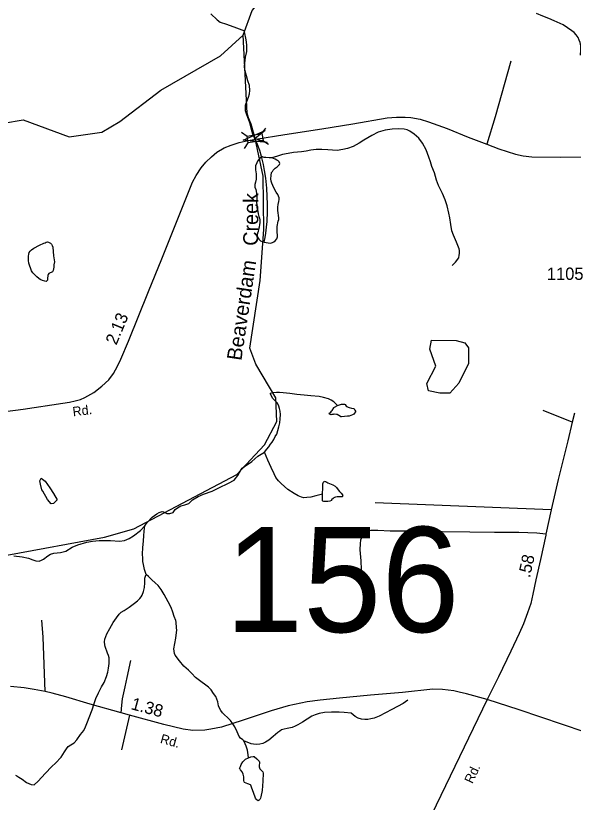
# Model space of a CAD drawing. Extents: x 2206922 to 2357709, y 510027 to 673830.
# Drawn here: x 2224516 to 2230172, y 549625 to 557602 of the extents above; entities that cross this region are included whole.
import ezdxf

# ---------------------------------------------------------------- set-up
doc = ezdxf.new("R2010")
doc.units = 0
for name, color, linetype in [('Exist Hydrographic Creek Single Shore', 7, 'Continuous'), ('Exist Hydrographic Creek Single Shore Label', 7, 'Continuous'), ('Exist Hydrographic Misc Water Feature', 7, 'Continuous'), ('Exist Hydrographic Pond Under 1500 Sq Ft', 7, 'Continuous'), ('Exist Road Non-System Type 51', 7, 'Continuous'), ('Exist Road Secondary Mileage Hundredths English Label', 7, 'Continuous'), ('Exist Road Secondary Structure Standard Bridge Attributed CELL', 7, 'Continuous'), ('Exist Road Secondary Structure Standard Bridge CELL', 7, 'Continuous'), ('Exist Road Secondary Structure Standard Bridge Number Label', 7, 'Continuous'), ('Exist Road Secondary Type 51 Attributed', 7, 'Continuous'), ('Exist Road Secondary Type 51 Label', 7, 'Continuous'), ('Exist Road Secondary Type 51 Number Label', 7, 'Continuous')]:
    doc.layers.add(name, color=color, linetype=linetype)

msp = doc.modelspace()

# ---------------------------------------------------------------- linework, layer by layer
at = {"layer": 'Exist Hydrographic Creek Single Shore'}
for points in [[(2226824.2, 557404.7), (2226914.2, 557655.5), (2227368.2, 558177.7), (2227799.2, 558372.3)], [(2223926.2, 556098.8), (2224069.1, 556168.1), (2224391.1, 556512.5), (2224590.2, 556544.6), (2225058.1, 556374.4), (2225391.1, 556420.2), (2225573.2, 556528), (2225987.2, 556847.6), (2226593.1, 557196.2), (2226824.2, 557404.7)], [(2223955.1, 551959), (2224427.1, 552129.9), (2225416.1, 552313.3), (2225715.1, 552399), (2226760.2, 552948.7), (2227041.1, 553251.3), (2227164.2, 553485), (2227154.1, 553727.9), (2226951.1, 554066.6), (2226892.1, 554231.7), (2226994.2, 554915.1), (2227032.1, 555432.6), (2227027.2, 555973.9), (2226945, 556358.4), (2226903.2, 556503.4), (2226877.1, 556567.2), (2226864.2, 556613.5), (2226824.2, 557404.7)]]:
    msp.add_lwpolyline(points, dxfattribs=at)
at = {"layer": 'Exist Hydrographic Misc Water Feature'}
for points in [[(2226494.9, 557620.4), (2226561.1, 557560.9), (2226589, 557535.2), (2226655.7, 557515.8), (2226755.5, 557478.4), (2226835.7, 557449.3)], [(2230244.3, 557201.1), (2230248.2, 557253.2), (2230247.3, 557297.1), (2230241.2, 557328.9), (2230232.8, 557354.9), (2230220.5, 557380.7), (2230200.6, 557408.8), (2230180.7, 557432.5), (2230158.1, 557450.1), (2230067.7, 557509.5), (2229977.7, 557550.7), (2229923.4, 557572.3), (2229863.1, 557597.6), (2229798.7, 557625.1)], [(2227010.4, 556175.2), (2226991.7, 556234.7), (2226969, 556296.6), (2226922.4, 556400.1), (2226907.9, 556448.1), (2226889.6, 556514.2), (2226860.7, 556596), (2226848.4, 556637.6), (2226845.9, 556673.6), (2226848, 556695.6), (2226859.5, 556731.6), (2226877.5, 556775.9), (2226887, 556809.8), (2226890.4, 556843.7), (2226886.3, 556895.8), (2226872, 556941.8), (2226857.6, 556993.4), (2226841.2, 557053.5), (2226836.7, 557085.4), (2226840.2, 557121.4), (2226845.9, 557181.4), (2226859.7, 557237.7), (2226858.9, 557307.5), (2226854.3, 557357.2), (2226837.9, 557439.3), (2226835.7, 557449.3)], [(2228944.4, 555067.5), (2228978.1, 555103.8), (2229009.6, 555146.1), (2229015.4, 555172), (2229019.1, 555192.1), (2229017, 555220), (2229015, 555236.1), (2228986.3, 555303.7), (2228955.7, 555377.7), (2228939.5, 555421.5), (2228930.7, 555483.2), (2228920.5, 555551.2), (2228910, 555599), (2228893.4, 555674.9), (2228872.7, 555734.5), (2228846.2, 555800.5), (2228805.6, 555880), (2228785.1, 555933.8), (2228763, 556009.7), (2228736.1, 556073.4), (2228724.2, 556119), (2228707.4, 556169), (2228681, 556242.7), (2228642.2, 556310.6), (2228605.9, 556360.3), (2228557.5, 556399.6), (2228515.3, 556429.5), (2228485.1, 556445), (2228455, 556452.8), (2228397, 556454.2), (2228335.4, 556451.7), (2228263.5, 556441.1), (2228193.7, 556420.8), (2228128.1, 556386.1), (2228046.3, 556339.6), (2227998.7, 556309.1), (2227938.7, 556274.8), (2227883.1, 556254.4), (2227834.9, 556243.8), (2227777.5, 556233.4), (2227683, 556242.8), (2227621.7, 556244), (2227563.4, 556243.8), (2227509.5, 556237.4), (2227461.5, 556226.7), (2227413.7, 556220.6), (2227333.8, 556213.6), (2227279.8, 556203.5), (2227223.6, 556192.9), (2227172.2, 556176.4), (2227113.9, 556162)], [(2227010.4, 556175.2), (2226996.2, 556159.1), (2226982.5, 556142.9), (2226968.8, 556126.7), (2226960.6, 556108.9), (2226948.9, 556078.6), (2226947.2, 556056.5), (2226947.2, 556038.7), (2226953.4, 555996.8), (2226955.8, 555970.9), (2226956.1, 555942.9), (2226946.6, 555914.8), (2226940.5, 555890.5), (2226942.5, 555864.7), (2226950.9, 555840.7), (2226955.2, 555821), (2226959.1, 555798.9), (2226961.2, 555773), (2226961.6, 555747), (2226959.9, 555707.1), (2226960.2, 555684.8), (2226960.6, 555668.9), (2226962.4, 555656.9), (2226964.7, 555645.2), (2226970.6, 555617.1), (2226976.8, 555593.1), (2226983.1, 555565.3), (2226987.2, 555549.3), (2226991.5, 555533.3), (2226993.6, 555515.5), (2226993.8, 555501.3), (2226989.9, 555483.2), (2226983.9, 555457.3), (2226978.2, 555433.5), (2226974.5, 555413.4), (2226968.6, 555395.2), (2226966.7, 555377.2), (2226969, 555355.4), (2226974.9, 555345.2), (2226982.7, 555335.5), (2226999.3, 555319.6), (2227017, 555311.6), (2227037.3, 555305.8)], [(2227113.9, 556162), (2227085.9, 556161.7), (2227053.9, 556163.7), (2227036.4, 556165.2), (2227010.4, 556175.2)], [(2227037.3, 555305.8), (2227047.1, 555351.7), (2227054.3, 555398.1), (2227059.8, 555456.1), (2227065.1, 555514), (2227070.7, 555613.7), (2227070.1, 555691.7), (2227067.4, 555770), (2227064.9, 555851.9), (2227051.6, 555953.6), (2227041.1, 556033.5), (2227030.7, 556093.5), (2227014.1, 556161.3), (2227010.4, 556175.2)], [(2227037.3, 555305.8), (2227054.9, 555301.9), (2227077.2, 555298.1), (2227101.2, 555294.5), (2227120.9, 555300.4), (2227133.4, 555308.7), (2227147, 555318.8), (2227163.2, 555338.7), (2227170.5, 555360.7), (2227172.6, 555381), (2227168.7, 555402.7), (2227168.1, 555417), (2227168.3, 555440.9), (2227169.7, 555463), (2227171.6, 555481), (2227175.7, 555501), (2227179.1, 555516.7), (2227183.5, 555534.7), (2227184.9, 555549.1), (2227182.6, 555579), (2227178.7, 555600.7), (2227176.5, 555630.7), (2227175.9, 555660.7), (2227178.1, 555686.8), (2227185.9, 555718.8), (2227189.4, 555737), (2227187.4, 555754.7), (2227181.4, 555772.7), (2227173.4, 555788.4), (2227159.1, 555812.5), (2227140.6, 555844.5), (2227124.4, 555880.2), (2227114.4, 555904), (2227108.4, 555924), (2227103.9, 555946.1), (2227105.7, 555982), (2227111.7, 556010.3), (2227119.7, 556022), (2227127.3, 556034.3), (2227137.3, 556046.1), (2227147.2, 556054.4), (2227168.9, 556070.5), (2227184.9, 556084.8), (2227190.8, 556094.4), (2227194.5, 556104.8), (2227188.4, 556118.7), (2227178.1, 556128.8), (2227164.6, 556138.6), (2227148.4, 556146.3), (2227113.9, 556162)], [(2224859, 554990), (2224852.8, 554986.1), (2224846.9, 554978.1), (2224840.7, 554970.1), (2224839.1, 554932.2), (2224839.3, 554920), (2224833.4, 554912), (2224823.3, 554907.8), (2224811.2, 554909.6), (2224787.6, 554915.6), (2224765.3, 554925.5), (2224749.5, 554937.2), (2224729, 554954.9), (2224706.8, 554976.9), (2224691, 554994.7), (2224676.5, 555014.7), (2224650, 555092.5), (2224645.7, 555118.3), (2224645.5, 555140.2), (2224645.3, 555164.2), (2224647.6, 555182.5), (2224650.9, 555200.3), (2224661.3, 555214.5), (2224674.8, 555228.7), (2224698.6, 555244.5), (2224758.5, 555275.2), (2224802.4, 555295.4), (2224814.1, 555299.8), (2224826.2, 555305.6), (2224840.1, 555308), (2224850, 555306.1), (2224862.7, 555300.1), (2224870.5, 555294.1), (2224880.3, 555284.1), (2224886.5, 555270.2), (2224892.8, 555254.2), (2224899.4, 555166.4), (2224907.8, 555106.4), (2224904.1, 555074.5), (2224902.5, 555052.4), (2224896.5, 555016.4), (2224890.8, 555004.3), (2224882.4, 555000.3), (2224859, 554990)], [(2227038.5, 553177), (2227064.5, 553205.1), (2227082.2, 553229.2), (2227101.6, 553257.1), (2227117.8, 553277.4), (2227133.6, 553303.4), (2227149.2, 553333.5), (2227163.4, 553359.7), (2227174.8, 553395.7), (2227186.3, 553431.7), (2227193.9, 553471.9), (2227199.7, 553512), (2227201.5, 553557.9), (2227197, 553589.8), (2227191, 553617.9), (2227184.7, 553641.5), (2227170.3, 553671.7), (2227124.2, 553719.3), (2227095.9, 553771)], [(2227778.5, 553648.5), (2227744.3, 553686.1), (2227716, 553704.2), (2227690.1, 553717.8), (2227639.7, 553729.5), (2227595.4, 553739), (2227509.5, 553746.3), (2227441.4, 553753.7), (2227367.6, 553761.2), (2227295.4, 553770.4), (2227228, 553778.2), (2227191.7, 553779.7), (2227161.7, 553781.3), (2227127.9, 553777.1), (2227095.9, 553771)], [(2227778.5, 553648.5), (2227822.2, 553661), (2227832.2, 553663.1), (2227840.4, 553663.1), (2227846.4, 553663), (2227852.3, 553661.3), (2227856.4, 553657.4), (2227866.5, 553643.3), (2227870.4, 553639.5), (2227874.3, 553637.3), (2227888.2, 553631.6), (2227898.7, 553627.6), (2227920.6, 553621.8), (2227943, 553618), (2227948.5, 553616), (2227956.5, 553600.1), (2227961.2, 553592.1), (2227962.7, 553588.3), (2227961.2, 553584), (2227953.2, 553571.9), (2227941.1, 553557.9), (2227937.4, 553556), (2227931.5, 553554), (2227897, 553541.8), (2227889.2, 553539.7), (2227883.1, 553539.4), (2227851.3, 553537.3), (2227819.5, 553534.9), (2227813.6, 553535), (2227809.5, 553538.8), (2227777.3, 553556.7), (2227773.4, 553556.4), (2227769.1, 553558.7), (2227747.1, 553560.3), (2227741.2, 553560.4), (2227737.1, 553558.2), (2227721.1, 553556.2), (2227713.1, 553554.1), (2227709.4, 553557.9), (2227703.3, 553562.1), (2227696.9, 553570), (2227701, 553573.8), (2227710.8, 553582.1), (2227720.7, 553590.3), (2227726.8, 553598.3), (2227742.6, 553624.3), (2227744.5, 553628.5), (2227750.6, 553632.4), (2227778.5, 553648.5)], [(2225825.4, 552429), (2225849, 552463.5), (2225900.6, 552515.8), (2225948, 552550.4), (2225972, 552564.2), (2226000.1, 552574.6), (2226014.5, 552568.8), (2226050.1, 552552.8), (2226079.9, 552553.2), (2226112.1, 552565.4), (2226134.2, 552595.7), (2226155.9, 552611.9), (2226191.2, 552630.1), (2226231.6, 552642.2), (2226273, 552656.6), (2226308.9, 552693), (2226366.9, 552727.3), (2226420.5, 552748), (2226508.4, 552780.5), (2226575.9, 552815.3), (2226673.7, 552861.8), (2226731.1, 552890.4), (2226770.7, 552938.8), (2226800, 552992.8), (2226814, 553013), (2226837.9, 553031.3), (2226911.4, 553079.8), (2226971, 553134.1), (2227038.5, 553177)], [(2227628, 552749.9), (2227561.8, 552733.1), (2227508.5, 552720.9), (2227470.3, 552714.5), (2227438.1, 552712.5), (2227413.9, 552718.1), (2227382.2, 552731.8), (2227339.9, 552755.3), (2227275.7, 552796.9), (2227241.5, 552826.4), (2227209.1, 552856.5), (2227181, 552886.2), (2227154.7, 552919.8), (2227136.5, 552955.9), (2227106.2, 553021.2), (2227073.5, 553093.1), (2227038.5, 553177)], [(2224874, 552653.2), (2224837.5, 552696.8), (2224792.8, 552780.6), (2224780.9, 552792.6), (2224766.1, 552852.4), (2224760.4, 552886.5), (2224775.7, 552910.5), (2224814.3, 552880.8), (2224860.6, 552815), (2224899.2, 552755.7), (2224935.7, 552691.7), (2224897.9, 552653.7), (2224874, 552653.2)], [(2227628, 552749.9), (2227631.7, 552817.9), (2227632.9, 552855.8), (2227639.1, 552869.9), (2227640.9, 552876.1), (2227644.6, 552880), (2227651, 552879.8), (2227656.9, 552878.1), (2227672.9, 552872), (2227683, 552866.1), (2227733.2, 552842.7), (2227754.9, 552830.9), (2227763.3, 552824.8), (2227769.3, 552817), (2227787.3, 552793.1), (2227799.6, 552777.2), (2227815.6, 552759.3), (2227830, 552743.3), (2227834.1, 552739.5), (2227831.8, 552731.7), (2227830, 552725.5), (2227825.9, 552721.2), (2227809.7, 552723.3), (2227798.2, 552723), (2227777.9, 552723.2), (2227759.9, 552720.7), (2227750.4, 552716.8), (2227744.3, 552712.9), (2227734.4, 552704.7), (2227724, 552696.5), (2227720.5, 552690.5), (2227718.6, 552686.7), (2227702.2, 552680.3), (2227680.3, 552674.3), (2227654.5, 552674.1), (2227642.4, 552675.9), (2227632.5, 552677.8), (2227628.4, 552683.7), (2227626.4, 552689.7), (2227626.2, 552695.8), (2227628, 552749.9)], [(2224498.3, 552122.7), (2224580.5, 552115.2), (2224644.9, 552101.8), (2224690.4, 552082), (2224720.6, 552074.2), (2224752.4, 552070.6), (2224776.8, 552078.7), (2224798.9, 552089.2), (2224842.2, 552125.2), (2224870.1, 552141.6), (2224902.5, 552149.7), (2224969.7, 552158.3), (2225025.9, 552170.9), (2225087.2, 552213.1), (2225147.1, 552235.7), (2225238.9, 552264.4), (2225294.9, 552273), (2225362.6, 552281.4), (2225476.8, 552280.5), (2225568.7, 552273.1), (2225620.8, 552279.8), (2225666.7, 552300), (2225712.2, 552326.4), (2225781.7, 552380.8), (2225825.4, 552429)], [(2225837.7, 551933.6), (2225820.7, 551987.3), (2225812.9, 552037.1), (2225806.3, 552067.3), (2225804.1, 552097.2), (2225801.6, 552143), (2225805.1, 552207), (2225812.9, 552277.2), (2225816, 552327), (2225819.9, 552375.1), (2225825.4, 552429)], [(2224512.9, 549899.6), (2224528.4, 549891.9), (2224548.5, 549879.9), (2224580.9, 549860), (2224626.9, 549826.8), (2224673.4, 549806.8), (2224703.4, 549801), (2224742.9, 549839.7), (2224816.5, 549916.2), (2224883.6, 549986.8), (2224921.3, 550022.8), (2224976.9, 550083.3), (2225010.7, 550137.5), (2225030.2, 550167.8), (2225047.8, 550189.9), (2225073.9, 550206.2), (2225110, 550228.4), (2225137.4, 550258.7), (2225172.9, 550310.9), (2225206.8, 550353.2), (2225224.2, 550389.1), (2225244.1, 550441.3), (2225261.5, 550485.6), (2225290.8, 550561.6), (2225310.5, 550625.9), (2225328.1, 550678), (2225355.6, 550736.3), (2225387, 550794.4), (2225414.7, 550840.5), (2225436.2, 550900.5), (2225449.7, 550944.7), (2225457.3, 550984.9), (2225462.9, 551030.7), (2225462.5, 551088.8), (2225456.1, 551114.9), (2225446.5, 551138.6), (2225423.5, 551204.6), (2225421.2, 551222.7), (2225416.9, 551250.5), (2225419.2, 551278.6), (2225440.5, 551332.6), (2225469.8, 551388.9), (2225503.7, 551449.1), (2225537.3, 551495.2), (2225566.6, 551531.7), (2225586.7, 551551.8), (2225616.4, 551570), (2225668.1, 551604.4), (2225720, 551642.8), (2225749.9, 551669.1), (2225775.6, 551693.2), (2225787.1, 551709.3), (2225797.1, 551725.2), (2225812.7, 551763.4), (2225820.7, 551803.6), (2225826.2, 551851.4), (2225825.4, 551885.6), (2225825.6, 551899.4), (2225831.1, 551917.6), (2225837.7, 551933.6)], [(2226830.6, 550246.5), (2226818.7, 550258.4), (2226796.5, 550276), (2226782.6, 550291.9), (2226763.7, 550337.7), (2226737.5, 550389.5), (2226719.4, 550421.4), (2226693.2, 550455.4), (2226669, 550480.9), (2226630.4, 550514.8), (2226614.2, 550532.6), (2226596.2, 550556.4), (2226582.4, 550578.4), (2226573.8, 550604), (2226565.6, 550644.1), (2226557.6, 550672.1), (2226544.9, 550698), (2226523, 550729.7), (2226498.8, 550765.3), (2226472.5, 550791.2), (2226444.2, 550810.9), (2226394, 550848.5), (2226339.7, 550892), (2226303.4, 550929.8), (2226268.9, 550965.5), (2226222.8, 551006.9), (2226176.6, 551058.9), (2226132.2, 551118.3), (2226125.8, 551134.3), (2226121.9, 551156.4), (2226121.5, 551180.3), (2226138.7, 551290.5), (2226147.9, 551346.2), (2226149.8, 551370.3), (2226147.7, 551394.1), (2226143.2, 551450.4), (2226138.7, 551470.1), (2226124.6, 551510), (2226110.4, 551551.9), (2226092, 551599.6), (2226063.3, 551657.5), (2226022.9, 551731.3), (2225990.3, 551782.9), (2225960.3, 551822.6), (2225931.8, 551850.5), (2225897.6, 551882), (2225861.5, 551915.8), (2225837.7, 551933.6)], [(2228494.8, 550659.7), (2228444.7, 550625.4), (2228331.3, 550564.7), (2228204.2, 550497.5), (2228150.5, 550478.9), (2228118.1, 550470.8), (2228086.5, 550464.6), (2228058.4, 550464.4), (2228024.2, 550466.3), (2227988.3, 550477.7), (2227958.1, 550493.6), (2227917.7, 550529.4), (2227848, 550536.6), (2227796.2, 550538.4), (2227719.9, 550537.7), (2227647.9, 550534.8), (2227594, 550524.7), (2227554.2, 550512.5), (2227518.5, 550497.9), (2227470.9, 550469.4), (2227425, 550439), (2227379.1, 550410.7), (2227351.2, 550396.7), (2227321.7, 550382.5), (2227269.4, 550372.1), (2227239.8, 550365.6), (2227213.6, 550359.4), (2227193.5, 550345.4), (2227174.2, 550331.3), (2227128.3, 550292.8), (2227082.4, 550254.3), (2227051, 550234.4), (2227022.9, 550219.9), (2226990.9, 550213.8), (2226961, 550209.4), (2226927.1, 550213.3), (2226902.9, 550219), (2226830.6, 550246.5)], [(2226876.3, 550077), (2226874.2, 550104.9), (2226871.8, 550128.8), (2226865.6, 550152.8), (2226861.1, 550174.6), (2226853.1, 550194.9), (2226844.7, 550216.4), (2226830.6, 550246.5)], [(2226876.3, 550077), (2226901.9, 550084.9), (2226923.9, 550089.3), (2226936, 550087.5), (2226960.4, 550065.5), (2226984.4, 550041.7), (2226988.2, 550031.7), (2226988.2, 550022), (2226986.8, 549999.9), (2226987, 549983.7), (2226990.9, 549965.6), (2227023.1, 549932), (2227025.4, 549920.3), (2227021.9, 549840.1), (2227014.7, 549744.3), (2227003.2, 549679.9), (2226997.5, 549666.2), (2226991.7, 549654.1), (2226983.9, 549645.9), (2226975.7, 549639.9), (2226965.7, 549645.9), (2226957.5, 549653.5), (2226949.5, 549665.7), (2226929.2, 549725.6), (2226912.6, 549769.4), (2226902.3, 549799.3), (2226898.4, 549801.2), (2226872, 549810.8), (2226852.1, 549818.7), (2226838.1, 549824.9), (2226832.4, 549830.6), (2226829.9, 549844.8), (2226829.7, 549884.5), (2226827.7, 549896.6), (2226821.5, 549908.5), (2226811.5, 549932.3), (2226795.1, 549954.2), (2226791.4, 549962.1), (2226786.9, 549968.4), (2226794.9, 549988.3), (2226802.9, 550008.2), (2226820.3, 550034.4), (2226845.9, 550060.9), (2226876.3, 550077)]]:
    msp.add_lwpolyline(points, dxfattribs=at)
at = {"layer": 'Exist Hydrographic Pond Under 1500 Sq Ft'}
msp.add_lwpolyline([(2228819.2, 553773), (2228703.1, 553798.3), (2228685.3, 553870.8), (2228776.1, 554049.4), (2228716.2, 554221.2), (2228732.2, 554312.7), (2228982.2, 554307.6), (2229073.2, 554282.8), (2229107.3, 554232.9), (2229108.3, 554075.5), (2229010.3, 553874.1), (2228919.2, 553774.3), (2228819.2, 553773)], dxfattribs=at)
at = {"layer": 'Exist Road Non-System Type 51'}
for p, q in [((2230160.5, 553480.2), (2229867.5, 553599.4)), ((2229947.8, 552589.2), (2228162, 552662.5)), ((2225669.1, 550507.6), (2225590.7, 550155.6))]:
    msp.add_line(p, q, dxfattribs=at)
for points in [[(2229537.1, 557139.4), (2229380.3, 556576.4), (2229293.7, 556298.3)], [(2229894.8, 552345.2), (2229800.4, 552352.9), (2229619.5, 552360.6), (2229371.3, 552360.6), (2229123.1, 552365.8), (2228841.3, 552368.4), (2228562.1, 552373.6), (2228315.4, 552375.3), (2228190.2, 552379.9), (2228117.8, 552381.6), (2228093.6, 552373.6), (2228074.1, 552366.7), (2228058, 552354), (2228041.9, 552340.2), (2228027, 552323), (2228019, 552301.1), (2228012.1, 552281.6), (2228009.8, 552249.4), (2228007.5, 552185), (2228016.7, 552072.4), (2228020.1, 551985), (2228020.1, 551915.4), (2228013.2, 551877.5)], [(2224815.3, 550748.9), (2224794.4, 551299), (2224781.3, 551470.4)], [(2225585.4, 550532.4), (2225592, 550610.9), (2225599.4, 550674.7), (2225626.5, 550796.7), (2225645.8, 550890.9), (2225684.2, 551061.1)]]:
    msp.add_lwpolyline(points, dxfattribs=at)
at = {"layer": 'Exist Road Secondary Structure Standard Bridge Attributed CELL'}
msp.add_lwpolyline([(2227067.4, 556314.6), (2226824.7, 556338.6), (2227046.9, 556439.2), (2226945, 556358.4)], close=True, dxfattribs=at)
at = {"layer": 'Exist Road Secondary Structure Standard Bridge CELL'}
for p, q in [((2226807.5, 556421.3), (2226863.7, 556381.3)), ((2227012.8, 556406.1), (2227052.8, 556462.3)), ((2226835.4, 556255.5), (2226875.4, 556311.7)), ((2227024.2, 556338), (2227080.4, 556298))]:
    msp.add_line(p, q, dxfattribs=at)
msp.add_lwpolyline([(2226863.7, 556381.3), (2227012.7, 556406.4), (2227024.4, 556336.8), (2226875.4, 556311.7)], close=True, dxfattribs=at)
at = {"layer": 'Exist Road Secondary Type 51 Attributed'}
for points in [[(2226952.6, 556349.4), (2227246.3, 556396.3), (2227619.9, 556454.9), (2227936.3, 556507), (2228285.2, 556565.6), (2228378.9, 556573.4), (2228466.1, 556573.4), (2228523.4, 556568.2), (2228618.4, 556551.3), (2228704.4, 556525.2), (2228891.8, 556457.5), (2229104, 556371.5), (2229293.7, 556298.3), (2229416.5, 556251.7), (2229584.7, 556197.6), (2229662.1, 556181.1), (2229752.6, 556170.3), (2230040, 556166.4), (2230789.5, 556171.3)], [(2224196.1, 553559.5), (2224593.2, 553612.9), (2224994.1, 553671.5), (2225061.8, 553682.6), (2225119.1, 553696.3), (2225172.5, 553711.3), (2225218, 553730.2), (2225307.9, 553782.3), (2225389.9, 553843.5), (2225460.2, 553909.9), (2225507.1, 553971.8), (2225548.7, 554047.3), (2225583.9, 554120.3), (2225659.4, 554302), (2225862.5, 554804.8), (2225996.9, 555135.7), (2226200.9, 555642.4), (2226310.3, 555913.4), (2226346.7, 555980.5), (2226397.5, 556058.5), (2226444.4, 556115.9), (2226500.4, 556171.3), (2226556.3, 556219.5), (2226631.8, 556263), (2226700.8, 556290.1), (2226782.9, 556314.9), (2226874, 556337), (2226952.6, 556349.4)], [(2230182.6, 553572.1), (2230160.5, 553480.2), (2230116.2, 553290.7), (2230018.6, 552897.3), (2229947.8, 552589.2), (2229894.8, 552345.2), (2229892.1, 552332.8), (2229837.9, 552086.4), (2229791.8, 551880.2), (2229760.8, 551736), (2229741.7, 551641.9), (2229708.4, 551545.8), (2229665.4, 551435.3), (2229622.2, 551335), (2229537.6, 551158.5), (2229412, 550895.6), (2229298.8, 550665.9)], [(2229298.8, 550665.9), (2229089.6, 550723.4), (2229013.3, 550740.5), (2228958.8, 550754.2), (2228845.1, 550769.9), (2228748.3, 550771.2), (2228438.4, 550739.8), (2228114.2, 550712.3), (2227800.4, 550680.9), (2227604.2, 550659.3), (2227470.9, 550642.3), (2227279.3, 550602.4), (2227108.7, 550551.4), (2226822.3, 550458.5), (2226602.7, 550387.9), (2226496.8, 550365.6), (2226434, 550355.1), (2226313.7, 550353.8), (2226213, 550365), (2226016.9, 550413.4), (2225669.1, 550507.6), (2225585.4, 550532.4), (2225271.6, 550620.1), (2225023.2, 550694), (2224884.6, 550731.9), (2224815.3, 550748.9), (2224704.2, 550769.2), (2224603.5, 550784.9), (2224463.6, 550799.3)], [(2229298.8, 550665.9), (2228076.2, 548138.3)], [(2233239, 549296.6), (2233198.9, 549320.4), (2233124.7, 549362.5), (2233034.3, 549411.7), (2232924, 549462.8), (2232759.5, 549533.5), (2232665.3, 549564.6), (2232478.8, 549627.1), (2231929.7, 549802.6), (2231502.7, 549945), (2230502.5, 550264.7), (2229623, 550561.2), (2229298.8, 550665.9)]]:
    msp.add_lwpolyline(points, dxfattribs=at)

# ---------------------------------------------------------------- texts
at = {"layer": 'Exist Hydrographic Creek Single Shore Label'}
for s, rotation, p in [('Creek', 89.56538, (2226973.4, 555268.3)), ('Beaverdam', 81.50139, (2226804.8, 554098))]:
    msp.add_text(s, height=150, rotation=rotation, dxfattribs=at).set_placement(p)
at = {"layer": 'Exist Road Secondary Mileage Hundredths English Label'}
for s, rotation, p in [('2.13', 67.28889, (2225536.9, 554255)), ('.58', 77.39708, (2229731.2, 551895.6)), ('1.38', 344.84651, (2225677.6, 550570))]:
    msp.add_text(s, height=125, rotation=rotation, dxfattribs=at).set_placement(p)
at = {"layer": 'Exist Road Secondary Structure Standard Bridge Number Label'}
msp.add_text('156', height=1066.27, dxfattribs=at).set_placement((2226639, 551351))
at = {"layer": 'Exist Road Secondary Type 51 Label'}
for rotation, p in [(7.05179, (2225098.9, 553538.5)), (344.48839, (2225975.4, 550228)), (64.58183, (2229147.6, 549807.4))]:
    msp.add_text('Rd.', height=95, rotation=rotation, dxfattribs=at).set_placement(p)
at = {"layer": 'Exist Road Secondary Type 51 Number Label'}
msp.add_text('1105', height=125, dxfattribs=at).set_placement((2229903.7, 554922.7))

doc.saveas('drawing.dxf')
